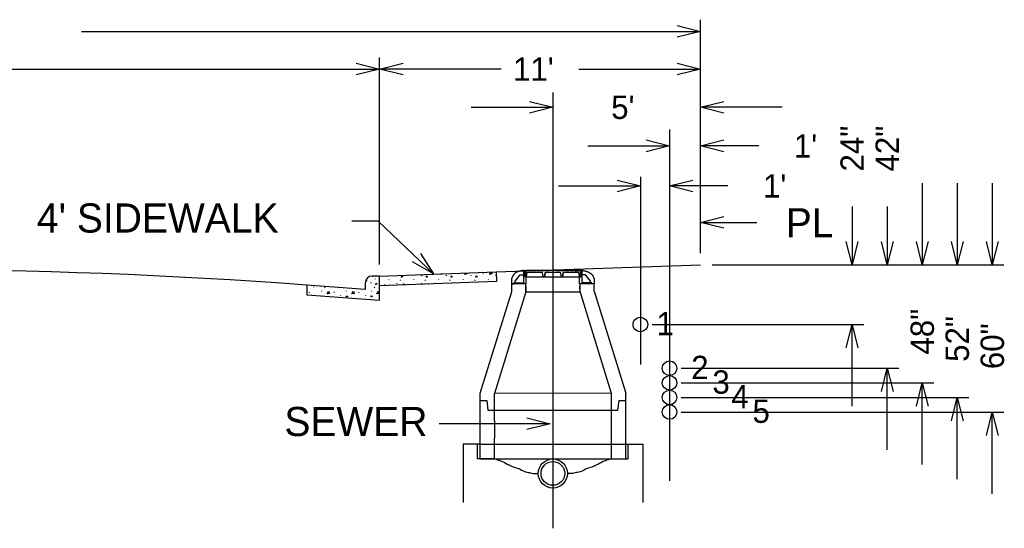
# Model space of a CAD drawing. Extents: x 524397 to 525117, y 3701341 to 3701821.
# Drawn here: x 524798.7 to 524866.2, y 3701543.5 to 3701578.4 of the extents above; entities that cross this region are included whole.
import ezdxf

# ---------------------------------------------------------------- set-up
doc = ezdxf.new("R2010")
doc.units = 0
doc.layers.add('Level 11', color=7, linetype='Continuous')

msp = doc.modelspace()

# ---------------------------------------------------------------- linework, layer by layer
at = {"layer": 'Level 11'}
for p, q in [((524843.784, 3701577.985), (524845.385, 3701577.585)), ((524845.385, 3701562.373), (524845.385, 3701578.385)), ((524802.962, 3701577.585), (524845.385, 3701577.585)), ((524845.385, 3701577.585), (524843.784, 3701577.185)), ((524821.797, 3701575.396), (524823.398, 3701574.995)), ((524823.398, 3701561.605), (524823.398, 3701575.796)), ((524823.398, 3701574.995), (524824.999, 3701575.396)), ((524843.784, 3701575.396), (524845.385, 3701574.995)), ((524845.385, 3701562.373), (524845.385, 3701575.796)), ((524793.051, 3701574.995), (524823.398, 3701574.995)), ((524823.398, 3701574.995), (524821.797, 3701574.595)), ((524831.738, 3701574.995), (524823.398, 3701574.995)), ((524824.999, 3701574.595), (524823.398, 3701574.995)), ((524837.045, 3701574.995), (524845.385, 3701574.995)), ((524845.385, 3701574.995), (524843.784, 3701574.595)), ((524835.269, 3701573.384), (524835.269, 3701543.507)), ((524833.668, 3701572.779), (524835.269, 3701572.379)), ((524845.385, 3701572.379), (524846.986, 3701572.779)), ((524829.666, 3701572.379), (524835.269, 3701572.379)), ((524835.269, 3701572.379), (524833.668, 3701571.978)), ((524850.988, 3701572.379), (524845.385, 3701572.379)), ((524846.986, 3701571.978), (524845.385, 3701572.379)), ((524843.269, 3701570.846), (524843.269, 3701546.766)), ((524841.668, 3701570.135), (524843.269, 3701569.735)), ((524845.385, 3701569.735), (524846.986, 3701570.135)), ((524837.666, 3701569.735), (524843.269, 3701569.735)), ((524843.269, 3701569.735), (524841.668, 3701569.334)), ((524849.387, 3701569.735), (524845.385, 3701569.735)), ((524846.986, 3701569.334), (524845.385, 3701569.735)), ((524839.668, 3701567.385), (524841.269, 3701566.985)), ((524841.269, 3701567.62), (524841.269, 3701554.745)), ((524843.269, 3701566.985), (524844.87, 3701567.385)), ((524860.587, 3701567.175), (524860.587, 3701561.572)), ((524862.988, 3701567.175), (524862.988, 3701561.572)), ((524865.389, 3701567.175), (524865.389, 3701561.572)), ((524835.666, 3701566.985), (524841.269, 3701566.985)), ((524841.269, 3701566.985), (524839.668, 3701566.585)), ((524847.272, 3701566.985), (524843.269, 3701566.985)), ((524844.87, 3701566.585), (524843.269, 3701566.985)), ((524843.269, 3701565.468), (524843.269, 3701563.922)), ((524855.784, 3701565.575), (524855.784, 3701561.572)), ((524858.185, 3701565.575), (524858.185, 3701561.572)), ((524823.304, 3701564.578), (524821.5, 3701564.578)), ((524827.083, 3701560.967), (524823.304, 3701564.578)), ((524845.385, 3701564.478), (524846.986, 3701564.878)), ((524845.385, 3701564.478), (524849.261, 3701564.478)), ((524846.986, 3701564.078), (524845.385, 3701564.478)), ((524855.784, 3701561.572), (524855.384, 3701563.173)), ((524856.184, 3701563.173), (524855.784, 3701561.572)), ((524858.185, 3701561.572), (524857.785, 3701563.173)), ((524858.585, 3701563.173), (524858.185, 3701561.572)), ((524860.587, 3701561.572), (524860.186, 3701563.173)), ((524860.987, 3701563.173), (524860.587, 3701561.572)), ((524862.988, 3701561.572), (524862.588, 3701563.173)), ((524863.388, 3701563.173), (524862.988, 3701561.572)), ((524865.389, 3701561.572), (524864.989, 3701563.173)), ((524865.79, 3701563.173), (524865.389, 3701561.572)), ((524827.083, 3701560.967), (524825.649, 3701561.783)), ((524826.202, 3701562.362), (524827.083, 3701560.967)), ((524823.398, 3701560.804), (524831.393, 3701561.084)), ((524831.393, 3701561.084), (524845.385, 3701561.572)), ((524831.393, 3701561.084), (524831.416, 3701560.424)), ((524833.27, 3701561.177), (524833.27, 3701561.177)), ((524833.27, 3701561.177), (524833.354, 3701561.177)), ((524833.27, 3701560.886), (524833.27, 3701561.177)), ((524833.354, 3701560.761), (524833.354, 3701561.177)), ((524833.395, 3701561.177), (524833.395, 3701560.761)), ((524833.438, 3701561.177), (524833.395, 3701561.177)), ((524833.395, 3701561.177), (524833.438, 3701561.177)), ((524833.395, 3701560.761), (524833.395, 3701561.177)), ((524833.438, 3701561.177), (524833.453, 3701561.219)), ((524833.438, 3701561.177), (524833.453, 3701561.219)), ((524833.453, 3701561.219), (524833.515, 3701561.219)), ((524833.453, 3701561.219), (524833.515, 3701561.219)), ((524833.53, 3701561.177), (524833.515, 3701561.219)), ((524833.515, 3701561.219), (524833.53, 3701561.177)), ((524833.761, 3701561.177), (524833.53, 3701561.177)), ((524833.53, 3701561.177), (524833.761, 3701561.177)), ((524833.761, 3701561.177), (524833.777, 3701561.219)), ((524833.761, 3701561.177), (524833.777, 3701561.219)), ((524833.777, 3701561.219), (524833.836, 3701561.219)), ((524833.777, 3701561.219), (524833.836, 3701561.219)), ((524833.851, 3701561.177), (524833.836, 3701561.219)), ((524833.836, 3701561.219), (524833.851, 3701561.177)), ((524834.078, 3701561.177), (524833.851, 3701561.177)), ((524833.851, 3701561.177), (524834.078, 3701561.177)), ((524834.078, 3701561.177), (524834.093, 3701561.219)), ((524834.078, 3701561.177), (524834.093, 3701561.219)), ((524834.093, 3701561.219), (524834.16, 3701561.219)), ((524834.093, 3701561.219), (524834.16, 3701561.219)), ((524834.176, 3701561.177), (524834.16, 3701561.219)), ((524834.16, 3701561.219), (524834.176, 3701561.177)), ((524834.405, 3701561.177), (524834.176, 3701561.177)), ((524834.176, 3701561.177), (524834.405, 3701561.177)), ((524834.405, 3701561.177), (524834.42, 3701561.219)), ((524834.405, 3701561.177), (524834.42, 3701561.219)), ((524834.42, 3701561.219), (524834.485, 3701561.219)), ((524834.42, 3701561.219), (524834.485, 3701561.219)), ((524834.5, 3701561.177), (524834.485, 3701561.219)), ((524834.485, 3701561.219), (524834.5, 3701561.177)), ((524834.727, 3701561.177), (524834.5, 3701561.177)), ((524834.5, 3701561.177), (524834.727, 3701561.177)), ((524834.727, 3701561.177), (524834.743, 3701561.219)), ((524834.727, 3701561.177), (524834.743, 3701561.219)), ((524834.743, 3701561.219), (524834.801, 3701561.219)), ((524834.743, 3701561.219), (524834.801, 3701561.219)), ((524834.816, 3701561.177), (524834.801, 3701561.219)), ((524834.801, 3701561.219), (524834.816, 3701561.177)), ((524835.003, 3701561.177), (524834.816, 3701561.177)), ((524834.816, 3701561.177), (524835.003, 3701561.177)), ((524835.003, 3701561.177), (524835.018, 3701561.219)), ((524835.003, 3701561.177), (524835.018, 3701561.219)), ((524835.018, 3701561.219), (524835.269, 3701561.219)), ((524835.018, 3701561.219), (524835.52, 3701561.219)), ((524835.52, 3701561.219), (524835.269, 3701561.219)), ((524835.536, 3701561.177), (524835.52, 3701561.219)), ((524835.52, 3701561.219), (524835.536, 3701561.177)), ((524835.722, 3701561.177), (524835.536, 3701561.177)), ((524835.536, 3701561.177), (524835.722, 3701561.177)), ((524835.722, 3701561.177), (524835.737, 3701561.219)), ((524835.722, 3701561.177), (524835.737, 3701561.219)), ((524835.795, 3701561.219), (524835.737, 3701561.219)), ((524835.737, 3701561.219), (524835.795, 3701561.219)), ((524835.811, 3701561.177), (524835.795, 3701561.219)), ((524835.795, 3701561.219), (524835.811, 3701561.177)), ((524836.038, 3701561.177), (524835.811, 3701561.177)), ((524835.811, 3701561.177), (524836.038, 3701561.177)), ((524836.038, 3701561.177), (524836.053, 3701561.219)), ((524836.038, 3701561.177), (524836.053, 3701561.219)), ((524836.118, 3701561.219), (524836.053, 3701561.219)), ((524836.053, 3701561.219), (524836.118, 3701561.219)), ((524836.133, 3701561.177), (524836.118, 3701561.219)), ((524836.118, 3701561.219), (524836.133, 3701561.177)), ((524836.362, 3701561.177), (524836.133, 3701561.177)), ((524836.133, 3701561.177), (524836.362, 3701561.177)), ((524836.362, 3701561.177), (524836.377, 3701561.219)), ((524836.362, 3701561.177), (524836.377, 3701561.219)), ((524836.446, 3701561.219), (524836.377, 3701561.219)), ((524836.377, 3701561.219), (524836.446, 3701561.219)), ((524836.46, 3701561.177), (524836.446, 3701561.219)), ((524836.446, 3701561.219), (524836.46, 3701561.177)), ((524836.687, 3701561.177), (524836.46, 3701561.177)), ((524836.46, 3701561.177), (524836.687, 3701561.177)), ((524836.687, 3701561.177), (524836.702, 3701561.219)), ((524836.687, 3701561.177), (524836.702, 3701561.219)), ((524836.761, 3701561.219), (524836.702, 3701561.219)), ((524836.702, 3701561.219), (524836.761, 3701561.219)), ((524836.776, 3701561.177), (524836.761, 3701561.219)), ((524836.761, 3701561.219), (524836.776, 3701561.177)), ((524837.008, 3701561.177), (524836.776, 3701561.177)), ((524836.776, 3701561.177), (524836.831, 3701561.177)), ((524836.831, 3701561.177), (524836.831, 3701561.053)), ((524836.831, 3701561.177), (524836.831, 3701561.053)), ((524836.955, 3701561.177), (524836.955, 3701561.053)), ((524836.955, 3701561.177), (524837.008, 3701561.177)), ((524836.955, 3701561.053), (524836.955, 3701561.177)), ((524837.008, 3701561.177), (524837.023, 3701561.219)), ((524837.008, 3701561.177), (524837.023, 3701561.219)), ((524837.085, 3701561.219), (524837.023, 3701561.219)), ((524837.023, 3701561.219), (524837.085, 3701561.219)), ((524837.1, 3701561.177), (524837.085, 3701561.219)), ((524837.085, 3701561.219), (524837.1, 3701561.177)), ((524837.142, 3701561.177), (524837.1, 3701561.177)), ((524837.1, 3701561.177), (524837.142, 3701561.177)), ((524837.142, 3701561.177), (524837.142, 3701560.761)), ((524837.142, 3701561.177), (524837.142, 3701560.761)), ((524837.184, 3701560.761), (524837.184, 3701561.177)), ((524837.268, 3701561.177), (524837.184, 3701561.177)), ((524837.268, 3701560.886), (524837.268, 3701561.177)), ((524846.185, 3701561.572), (524856.584, 3701561.572)), ((524846.185, 3701561.572), (524858.986, 3701561.572)), ((524846.185, 3701561.572), (524861.387, 3701561.572)), ((524846.185, 3701561.572), (524863.788, 3701561.572)), ((524846.185, 3701561.572), (524866.19, 3701561.572)), ((524823.398, 3701560.804), (524822.885, 3701560.804)), ((524822.885, 3701560.804), (524822.898, 3701560.804)), ((524823.104, 3701560.591), (524823.118, 3701560.623)), ((524823.398, 3701559.143), (524823.398, 3701560.804)), ((524823.398, 3701560.144), (524823.398, 3701560.804)), ((524831.416, 3701560.424), (524823.398, 3701560.144)), ((524824.03, 3701560.538), (524824.045, 3701560.57)), ((524824.554, 3701560.845), (524824.555, 3701560.829)), ((524824.794, 3701560.538), (524824.808, 3701560.517)), ((524824.808, 3701560.53), (524824.823, 3701560.509)), ((524825.732, 3701560.538), (524825.746, 3701560.57)), ((524826.253, 3701560.861), (524826.257, 3701560.829)), ((524826.496, 3701560.538), (524826.51, 3701560.517)), ((524826.51, 3701560.53), (524826.524, 3701560.509)), ((524827.433, 3701560.538), (524827.448, 3701560.57)), ((524827.955, 3701560.861), (524827.958, 3701560.829)), ((524828.197, 3701560.538), (524828.211, 3701560.517)), ((524828.211, 3701560.53), (524828.226, 3701560.509)), ((524828.812, 3701560.95), (524828.826, 3701560.982)), ((524829.135, 3701560.538), (524829.149, 3701560.57)), ((524829.656, 3701560.861), (524829.66, 3701560.829)), ((524829.899, 3701560.538), (524829.913, 3701560.517)), ((524829.913, 3701560.53), (524829.927, 3701560.509)), ((524830.513, 3701560.95), (524830.527, 3701560.982)), ((524830.836, 3701560.538), (524830.851, 3701560.57)), ((524831.358, 3701560.861), (524831.361, 3701560.829)), ((524832.687, 3701560.345), (524832.688, 3701560.449)), ((524832.688, 3701560.449), (524833.037, 3701560.887)), ((524833.037, 3701560.887), (524833.27, 3701560.886)), ((524833.27, 3701560.345), (524833.27, 3701560.886)), ((524833.437, 3701560.761), (524833.354, 3701560.761)), ((524833.395, 3701560.761), (524837.142, 3701560.761)), ((524833.437, 3701560.761), (524833.395, 3701560.761)), ((524833.437, 3701560.761), (524833.488, 3701561.053)), ((524833.488, 3701561.053), (524833.437, 3701560.761)), ((524833.437, 3701560.261), (524833.437, 3701560.761)), ((524834.551, 3701561.053), (524833.488, 3701561.053)), ((524834.551, 3701561.053), (524833.488, 3701561.053)), ((524834.603, 3701560.761), (524834.551, 3701561.053)), ((524834.603, 3701560.761), (524834.551, 3701561.053)), ((524834.686, 3701560.761), (524834.603, 3701560.761)), ((524834.686, 3701560.761), (524834.738, 3701561.053)), ((524834.738, 3701561.053), (524834.686, 3701560.761)), ((524835.8, 3701561.053), (524834.738, 3701561.053)), ((524835.8, 3701561.053), (524834.738, 3701561.053)), ((524835.852, 3701560.761), (524835.8, 3701561.053)), ((524835.852, 3701560.761), (524835.8, 3701561.053)), ((524835.935, 3701560.761), (524835.852, 3701560.761)), ((524835.935, 3701560.761), (524835.986, 3701561.053)), ((524835.986, 3701561.053), (524835.935, 3701560.761)), ((524837.05, 3701561.053), (524835.986, 3701561.053)), ((524836.831, 3701561.053), (524835.986, 3701561.053)), ((524837.05, 3701561.053), (524836.955, 3701561.053)), ((524837.101, 3701560.761), (524837.05, 3701561.053)), ((524837.101, 3701560.761), (524837.05, 3701561.053)), ((524837.101, 3701560.261), (524837.101, 3701560.761)), ((524837.101, 3701560.761), (524837.184, 3701560.761)), ((524837.142, 3701560.761), (524837.101, 3701560.761)), ((524837.501, 3701560.887), (524837.268, 3701560.886)), ((524837.268, 3701560.345), (524837.268, 3701560.886)), ((524837.85, 3701560.449), (524837.501, 3701560.887)), ((524837.851, 3701560.345), (524837.85, 3701560.449)), ((524822.398, 3701559.88), (524818.398, 3701560.182)), ((524818.398, 3701560.182), (524818.398, 3701559.52)), ((524818.575, 3701559.688), (524818.589, 3701559.72)), ((524818.862, 3701560.033), (524818.877, 3701560.065)), ((524819.417, 3701559.77), (524819.431, 3701559.802)), ((524819.626, 3701560.033), (524819.64, 3701560.012)), ((524819.64, 3701560.025), (524819.655, 3701560.004)), ((524820.276, 3701559.688), (524820.29, 3701559.72)), ((524821.118, 3701559.77), (524821.132, 3701559.802)), ((524821.978, 3701559.688), (524821.992, 3701559.72)), ((524822.398, 3701560.342), (524822.398, 3701559.88)), ((524822.787, 3701560.356), (524822.79, 3701560.324)), ((524822.82, 3701559.77), (524822.834, 3701559.802)), ((524823.029, 3701560.033), (524823.043, 3701560.012)), ((524823.043, 3701560.025), (524823.058, 3701560.004)), ((524823.743, 3701560.193), (524823.757, 3701560.225)), ((524824.585, 3701560.275), (524824.599, 3701560.307)), ((524825.454, 3701560.216), (524825.458, 3701560.225)), ((524826.286, 3701560.275), (524826.3, 3701560.307)), ((524828.001, 3701560.305), (524828.002, 3701560.307)), ((524832.427, 3701559.728), (524830.276, 3701552.761)), ((524833.426, 3701559.729), (524831.276, 3701552.761)), ((524832.427, 3701560.261), (524832.427, 3701559.728)), ((524833.437, 3701560.261), (524832.427, 3701560.261)), ((524832.427, 3701560.261), (524832.604, 3701560.261)), ((524832.604, 3701560.261), (524832.604, 3701560.345)), ((524832.604, 3701560.345), (524832.687, 3701560.345)), ((524832.687, 3701560.345), (524833.27, 3701560.345)), ((524833.426, 3701559.729), (524833.426, 3701560.261)), ((524833.426, 3701560.095), (524833.426, 3701559.769)), ((524833.426, 3701559.729), (524837.112, 3701559.729)), ((524838.111, 3701560.261), (524837.101, 3701560.261)), ((524837.112, 3701560.261), (524837.112, 3701559.762)), ((524838.111, 3701560.261), (524837.112, 3701560.261)), ((524837.112, 3701559.928), (524837.112, 3701560.102)), ((524837.112, 3701559.762), (524839.271, 3701552.766)), ((524837.851, 3701560.345), (524837.268, 3701560.345)), ((524837.934, 3701560.345), (524837.851, 3701560.345)), ((524837.934, 3701560.261), (524837.934, 3701560.345)), ((524838.111, 3701560.261), (524837.934, 3701560.261)), ((524838.111, 3701559.762), (524838.111, 3701560.261)), ((524838.111, 3701559.762), (524840.271, 3701552.766)), ((524818.398, 3701559.52), (524823.398, 3701559.143)), ((524820.72, 3701559.461), (524820.734, 3701559.44)), ((524822.422, 3701559.461), (524822.436, 3701559.44)), ((524842.07, 3701557.483), (524856.584, 3701557.483)), ((524855.384, 3701555.882), (524855.784, 3701557.483)), ((524855.784, 3701551.879), (524855.784, 3701557.483)), ((524855.784, 3701557.483), (524856.184, 3701555.882)), ((524844.07, 3701554.483), (524858.986, 3701554.483)), ((524857.785, 3701552.882), (524858.185, 3701554.483)), ((524858.185, 3701548.879), (524858.185, 3701554.483)), ((524858.185, 3701554.483), (524858.585, 3701552.882)), ((524844.07, 3701553.483), (524861.387, 3701553.483)), ((524860.186, 3701551.882), (524860.587, 3701553.483)), ((524860.587, 3701547.879), (524860.587, 3701553.483)), ((524860.587, 3701553.483), (524860.987, 3701551.882)), ((524830.276, 3701552.761), (524830.276, 3701551.6)), ((524830.276, 3701552.468), (524830.276, 3701552.266)), ((524839.271, 3701552.765), (524831.276, 3701552.761)), ((524831.276, 3701551.6), (524831.276, 3701552.761)), ((524831.276, 3701552.266), (524831.276, 3701552.468)), ((524839.271, 3701552.766), (524839.271, 3701551.6)), ((524839.271, 3701552.766), (524839.271, 3701552.266)), ((524839.271, 3701552.468), (524839.271, 3701552.266)), ((524839.271, 3701552.468), (524839.271, 3701552.266)), ((524840.271, 3701552.266), (524840.271, 3701552.766)), ((524840.271, 3701552.266), (524840.271, 3701552.766)), ((524840.271, 3701548.269), (524840.271, 3701552.468)), ((524844.07, 3701552.483), (524863.788, 3701552.483)), ((524862.588, 3701550.882), (524862.988, 3701552.483)), ((524862.988, 3701546.879), (524862.988, 3701552.483)), ((524862.988, 3701552.483), (524863.388, 3701550.882)), ((524830.276, 3701552.266), (524830.734, 3701552.266)), ((524830.276, 3701552.266), (524830.734, 3701552.266)), ((524830.276, 3701552.266), (524830.276, 3701550.879)), ((524830.276, 3701551.878), (524830.276, 3701548.269)), ((524830.734, 3701552.266), (524830.818, 3701551.6)), ((524830.734, 3701552.266), (524830.818, 3701551.6)), ((524831.276, 3701550.879), (524831.276, 3701552.266)), ((524839.271, 3701552.266), (524839.271, 3701548.269)), ((524839.271, 3701552.266), (524839.271, 3701548.269)), ((524839.729, 3701551.6), (524839.812, 3701552.266)), ((524839.729, 3701551.6), (524839.812, 3701552.266)), ((524839.812, 3701552.266), (524840.271, 3701552.266)), ((524839.812, 3701552.266), (524840.271, 3701552.266)), ((524839.812, 3701552.266), (524840.271, 3701552.266)), ((524840.271, 3701551.6), (524840.271, 3701552.266)), ((524830.818, 3701551.6), (524831.276, 3701551.6)), ((524830.818, 3701551.6), (524831.276, 3701551.6)), ((524831.276, 3701551.6), (524839.271, 3701551.6)), ((524831.276, 3701551.6), (524839.271, 3701551.6)), ((524833.484, 3701551.082), (524835.085, 3701550.682)), ((524839.271, 3701551.6), (524839.729, 3701551.6)), ((524839.271, 3701551.6), (524839.729, 3701551.6)), ((524844.07, 3701551.483), (524866.19, 3701551.483)), ((524864.989, 3701549.882), (524865.389, 3701551.483)), ((524865.389, 3701545.879), (524865.389, 3701551.483)), ((524865.389, 3701551.483), (524865.79, 3701549.882)), ((524835.085, 3701550.682), (524827.467, 3701550.682)), ((524831.276, 3701550.879), (524831.276, 3701549.695)), ((524835.085, 3701550.682), (524833.484, 3701550.282)), ((524831.276, 3701548.269), (524831.276, 3701549.695)), ((524830.276, 3701549.268), (524829.111, 3701549.268)), ((524829.111, 3701549.268), (524829.111, 3701545.271)), ((524830.11, 3701548.269), (524830.11, 3701549.268)), ((524830.276, 3701549.268), (524840.271, 3701549.268)), ((524840.271, 3701549.268), (524841.437, 3701549.268)), ((524840.437, 3701548.269), (524840.437, 3701549.268)), ((524841.437, 3701549.268), (524841.437, 3701545.271)), ((524830.276, 3701548.269), (524830.11, 3701548.269)), ((524830.276, 3701548.269), (524830.11, 3701548.269)), ((524830.276, 3701548.269), (524831.276, 3701548.269)), ((524831.276, 3701548.269), (524830.276, 3701548.269)), ((524831.276, 3701548.269), (524830.276, 3701548.269)), ((524831.276, 3701548.269), (524839.271, 3701548.269)), ((524839.271, 3701548.269), (524840.271, 3701548.269)), ((524839.271, 3701548.269), (524840.271, 3701548.269)), ((524840.271, 3701548.269), (524840.437, 3701548.269))]:
    msp.add_line(p, q, dxfattribs=at)
for points in [[(524830.945, 3701560.914), (524830.967, 3701561.069)], [(524831.018, 3701561.07), (524831.101, 3701560.985), (524830.949, 3701560.915)], [(524822.462, 3701560.55), (524822.53, 3701560.48), (524822.425, 3701560.432)], [(524824.876, 3701560.723), (524824.919, 3701560.812), (524824.99, 3701560.759), (524824.876, 3701560.723)], [(524826.577, 3701560.723), (524826.62, 3701560.812), (524826.691, 3701560.759), (524826.577, 3701560.723)], [(524827.542, 3701560.914), (524827.547, 3701560.949)], [(524827.626, 3701560.952), (524827.546, 3701560.915)], [(524828.279, 3701560.723), (524828.322, 3701560.812), (524828.393, 3701560.759), (524828.279, 3701560.723)], [(524829.244, 3701560.914), (524829.257, 3701561.009)], [(524829.373, 3701561.013), (524829.399, 3701560.985), (524829.247, 3701560.915)], [(524829.98, 3701560.723), (524830.023, 3701560.812), (524830.094, 3701560.759), (524829.98, 3701560.723)], [(524819.797, 3701559.592), (524819.893, 3701559.773), (524819.967, 3701559.607), (524819.8, 3701559.592)], [(524821.498, 3701559.592), (524821.594, 3701559.773), (524821.669, 3701559.607), (524821.502, 3701559.592)], [(524823.111, 3701560.218), (524823.154, 3701560.307), (524823.225, 3701560.253), (524823.111, 3701560.218)], [(524823.2, 3701559.592), (524823.296, 3701559.773), (524823.37, 3701559.607), (524823.203, 3701559.592)], [(524823.398, 3701560.192), (524823.419, 3701560.145)], [(524825.019, 3701560.201), (524825.061, 3701560.279), (524825.094, 3701560.203)], [(524826.753, 3701560.261), (524826.762, 3701560.279), (524826.77, 3701560.262)], [(524819.427, 3701559.442), (524819.434, 3701559.457), (524819.458, 3701559.44)], [(524821.093, 3701559.369), (524821.136, 3701559.457), (524821.207, 3701559.404), (524821.093, 3701559.369)], [(524822.795, 3701559.369), (524822.837, 3701559.457), (524822.908, 3701559.404), (524822.795, 3701559.369)]]:
    msp.add_lwpolyline(points, dxfattribs=at)
for centre, radius in [((524841.269, 3701557.483), 0.5), ((524843.269, 3701554.483), 0.5), ((524843.269, 3701553.483), 0.5), ((524843.269, 3701552.483), 0.5), ((524843.269, 3701551.483), 0.5), ((524835.273, 3701547.269), 0.999), ((524835.273, 3701547.269), 0.814)]:
    msp.add_circle(centre, radius, dxfattribs=at)
for centre, radius, start, end in [((524790.397, 3701189.335), 371.902, 85.68204, 94.31764), ((524822.891, 3701560.31), 0.494, 89.23325, 176.29205)]:
    msp.add_arc(centre, radius, start, end, dxfattribs=at)
for points in [[(524833.27, 3701561.177), (524833.197, 3701561.176), (524833.118, 3701561.166), (524833.049, 3701561.154), (524832.99, 3701561.142), (524832.927, 3701561.114), (524832.868, 3701561.101), (524832.725, 3701561.021), (524832.621, 3701560.936), (524832.53, 3701560.817), (524832.454, 3701560.653), (524832.433, 3701560.421), (524832.427, 3701560.261)], [(524837.268, 3701561.177), (524837.34, 3701561.176), (524837.42, 3701561.166), (524837.489, 3701561.154), (524837.547, 3701561.142), (524837.611, 3701561.114), (524837.67, 3701561.101), (524837.813, 3701561.021), (524837.916, 3701560.936), (524838.008, 3701560.817), (524838.084, 3701560.653), (524838.105, 3701560.421), (524838.111, 3701560.261)], [(524831.276, 3701548.269), (524831.69, 3701548.144), (524832.194, 3701547.893), (524832.509, 3701547.746), (524832.928, 3701547.599), (524833.327, 3701547.41), (524833.664, 3701547.327), (524833.999, 3701547.264), (524834.274, 3701547.269)], [(524839.271, 3701548.269), (524838.857, 3701548.144), (524838.353, 3701547.893), (524838.038, 3701547.746), (524837.618, 3701547.599), (524837.219, 3701547.41), (524836.884, 3701547.327), (524836.547, 3701547.264), (524836.273, 3701547.269)]]:
    msp.add_spline(points, degree=3, dxfattribs=at)

# ---------------------------------------------------------------- texts
for s, height, p in [("11'", 1.601, (524832.538, 3701574.194)), ("5'", 1.601, (524839.268, 3701571.577)), ("1'", 1.601, (524851.789, 3701568.933)), ("1'", 1.601, (524849.673, 3701566.183)), ("4' SIDEWALK", 2, (524799.906, 3701563.787)), ('PL', 2, (524851.231, 3701563.46)), ('1', 1.601, (524842.372, 3701556.738)), ('2', 1.601, (524844.755, 3701553.738)), ('3', 1.601, (524846.205, 3701552.738)), ('4', 1.601, (524847.503, 3701551.738)), ('5', 1.601, (524848.954, 3701550.738)), ('SEWER', 2, (524816.868, 3701549.832))]:
    msp.add_text(s, height=height, dxfattribs=at).set_placement(p)
for s, p in [('24"', (524856.584, 3701567.974)), ('42"', (524858.986, 3701567.974)), ('48"', (524861.387, 3701555.421)), ('52"', (524863.788, 3701554.921)), ('60"', (524866.19, 3701554.421))]:
    msp.add_text(s, height=1.601, rotation=90, dxfattribs=at).set_placement(p)

doc.saveas('drawing.dxf')
